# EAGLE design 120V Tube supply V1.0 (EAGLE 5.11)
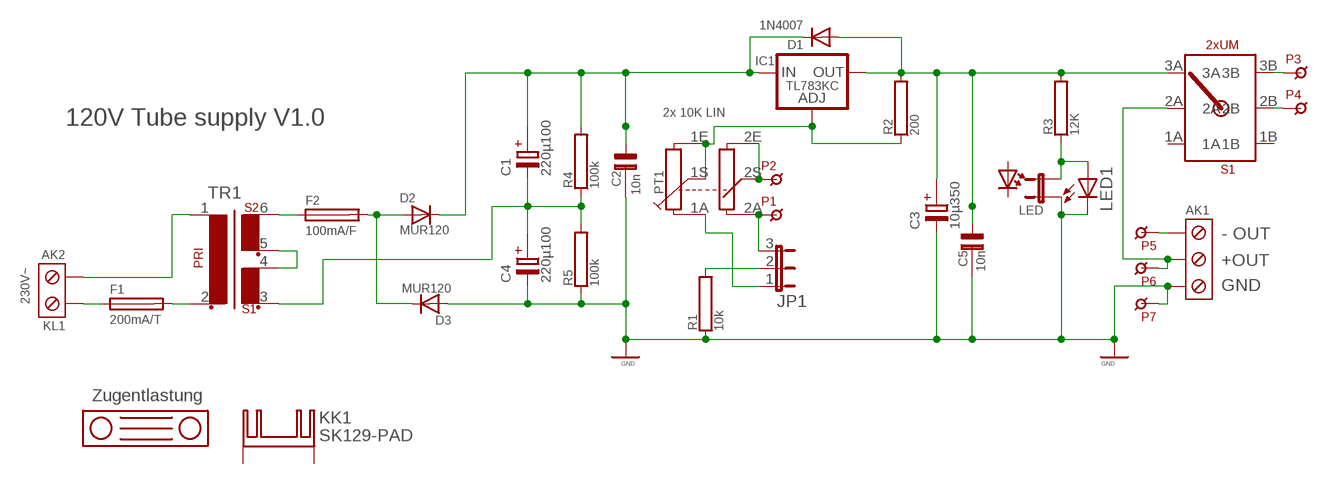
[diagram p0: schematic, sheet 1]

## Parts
AK1  KLEMME3STANDART  [KLEMME3]
AK2  KL1  KLEMME2RM5  [KLEMME2]
C1  220µ100  E7,5-16  [E7,5-16]
C2  10n  C2,5/55/2  [C2,5/5-2]
C3  10µ350  E5-13  [E5-13]
C4  220µ100  E7,5-16  [E7,5-16]
C5  10n  C2,5/55/2  [C2,5/5-2]
D1  1N4007  1N4004  [DO41-10]
D2  MUR120  MUR150RL  [DO41-10]
D3  MUR120  MUR150RL  [DO41-10]
F1  200mA/T  SH22,5A  [SH22,5A]
F2  100mA/F  SH22,5A  [SH22,5A]
IC1  TL783KC  LM317TS  [317TS]
JP1  JP2E  [JP2]
KK1  SK129-PAD  [SK129]
LED  JP1E  [JP1]
LED1  LED3MM  [LED3MM]
P1  AP1_GP13  [PUNKT13]
P2  AP1_GP13  [PUNKT13]
P3  AP1_GP13  [PUNKT13]
P4  AP1_GP13  [PUNKT13]
P5  AP1_GP13  [PUNKT13]
P6  AP1_GP13  [PUNKT13]
P7  AP1_GP13  [PUNKT13]
PT1  2x 10K LIN  BR2G20BU  [BR2G20BU]
R1  10k  0207/10RD  [0207/10]
R2  200  0207/10RD  [0207/10]
R3  12K  0414/15  [0414/15]
R4  100k  0207/10RD  [0207/10]
R5  100k  0207/10RD  [0207/10]
S1  2xUM  S-2PRINT  [S-2PRINT]
TR1  EI48-2  [EI48-2]
U$2  KAZU0442  [KAZU0442]

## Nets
GND: AK1.1 C2.1 C3.- C4.- C5.1 D3.A LED1.K(C) LED.1 P7.1 R1.1 R5.1
N$1: TR1.4 TR1.5
N$2: P3.1 S1.3B
N$3: F2.1 TR1.6
N$4: AK2.1 TR1.1
N$5: F1.2 TR1.2
N$6: AK2.2 F1.1
N$7: C3.+ C5.2 C5.3 D1.A IC1.2(OUT) R2.2 R3.2 S1.3A
N$8: D2.A D3.C F2.2
N$9: JP1.1 PT1.1A
N$10: C1.- C4.+ R4.1 R5.2 TR1.3
N$11: JP1.3 P1.1 PT1.2A
N$12: AK1.2 P6.1 S1.2A
N$13: LED1.A LED.2 R3.1
N$14: JP1.2 R1.2
N$15: IC1.1(ADJ) PT1.1E PT1.1S R2.1
N$16: P4.1 S1.2B
N$17: AK1.3 P5.1
N$19: P2.1 PT1.2E PT1.2S
VCC: C1.+ C2.2 C2.3 D1.C D2.C IC1.3(IN) R4.2
Unconnected: KK1.A2,5(K) KK1.B2,5(K) S1.1A S1.1B

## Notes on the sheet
- 120V Tube supply V1.0
- - OUT
- +OUT
- GND
- 230V~
- Zugentlastung

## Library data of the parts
AK1 = VERBINDE:KLEMME3
AK2 = VERBINDE:KLEMME2
C1 C4 = Elkos:E7,5-16
C2 C5 = CAP-Kondensatoren:C2,5/5
C3 = Elkos:E5-13
D1 = diode:1N4004: DIODE
D2 D3 = diode:MUR150RL: DIODE
F1 F2 = fuse:SH22,5A: FUSE HOLDER; MPN: 0031.7701.11; OC_FARNELL: unknown; OC_NEWARK: 04F1224
IC1 = v-reg:LM317TS: VOLTAGE REGULATOR
JP1 = jumper:JP2E: JUMPER
KK1 = heatsink:SK129-PAD: HEATSINK
LED = jumper:JP1E: JUMPER
LED1 = led:LED: LED
P1-P7 = VERBINDE:AP1_G
PT1 = Potentiometer-piher:BR2G20BU
R1 R2 R4 R5 = R:0207/10
R3 = R:0414/15
S1 = Schalter:S-2PRINT
TR1 = trafo:EI48-2: TRANSFORMER 1 primary winding, 2 secondary windings ERA
U$2 = MB:KAZU0442

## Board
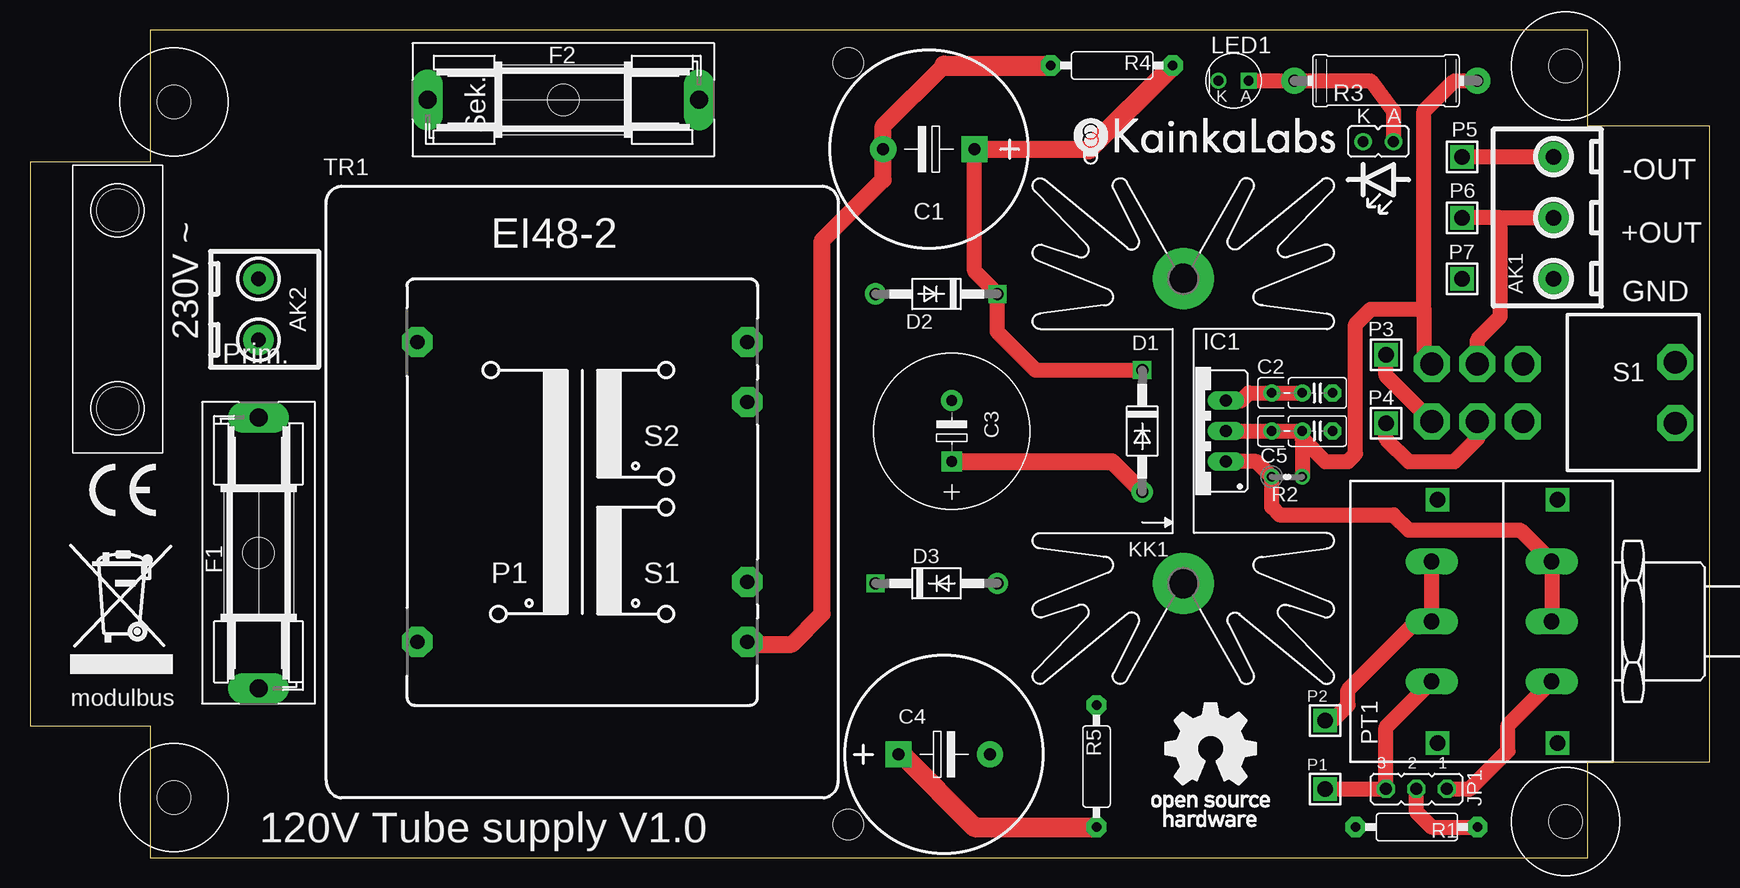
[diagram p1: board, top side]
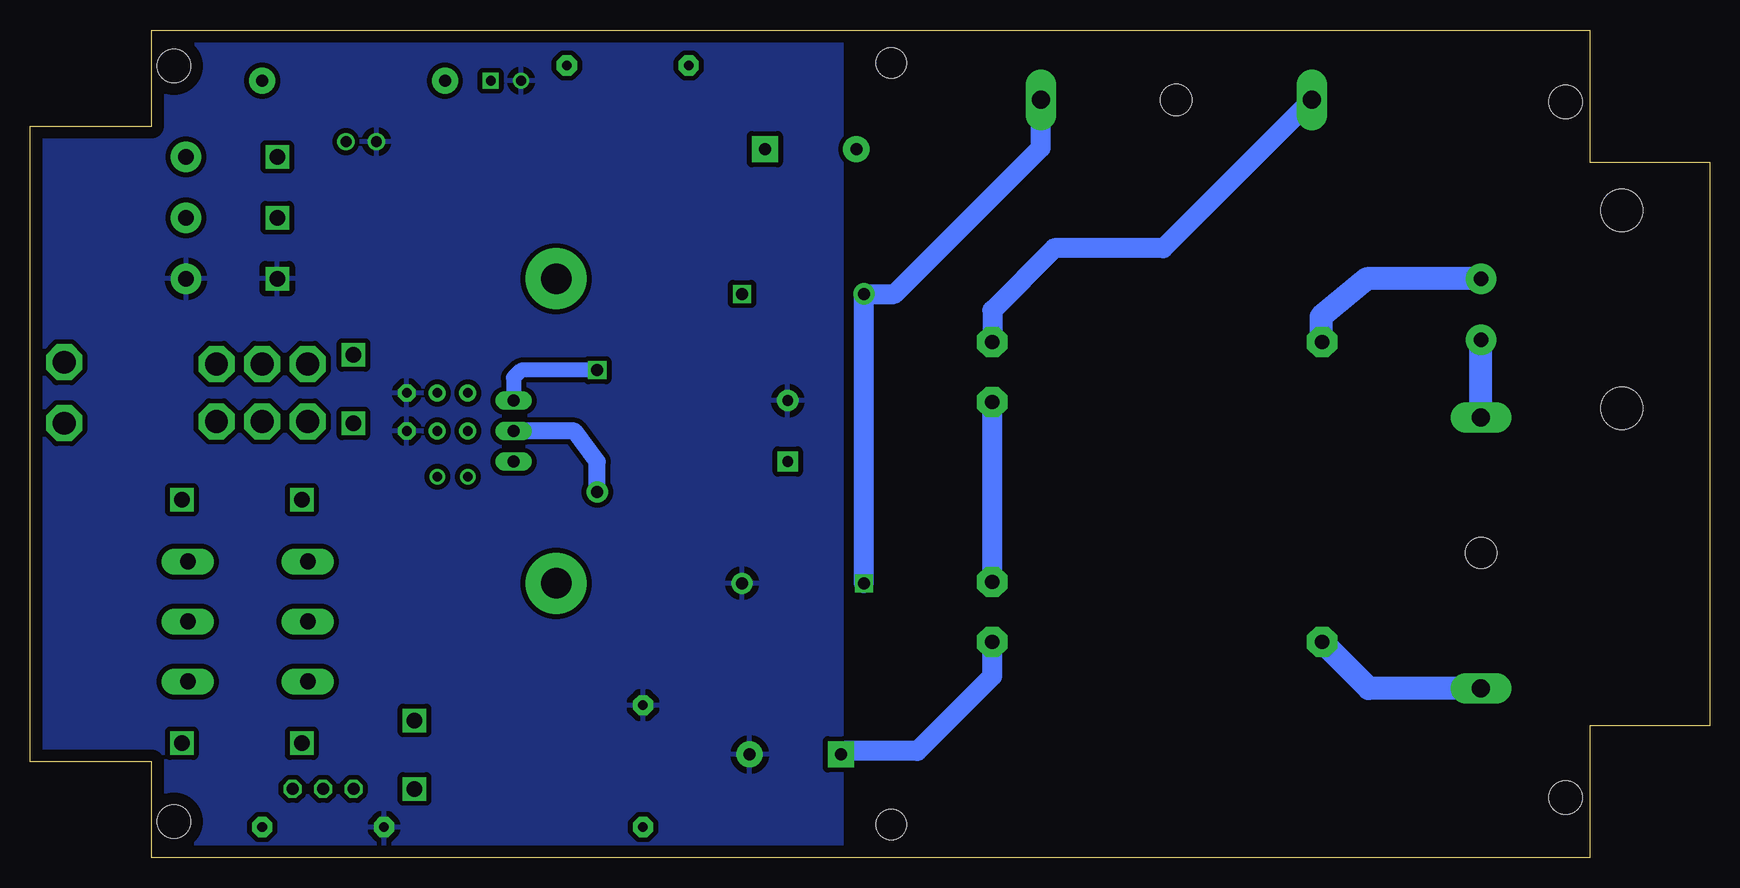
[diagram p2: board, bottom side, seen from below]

Size 140 x 69 mm. Coordinates in mm from the lower left corner, seen from the top.
Copper layers (1*16): Top 0.035mm / dielectric 1.5mm / Bottom 0.035mm
Design rules "default": minimum track width 10mil, minimum drill 23mil, track to track 8mil, track to pad 8mil, pad to pad 8mil, via to via 8mil, smd to smd 8mil, copper to edge 40mil, drill to drill 8mil, minimum pad ring 10mil, minimum via ring 8mil, stop-mask expansion 4mil, vias tented up to drill 0mil, thermal gap 20mil

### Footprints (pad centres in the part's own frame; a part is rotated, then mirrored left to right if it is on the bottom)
KLEMME3 = drill 1.3 pad 2.54 round: 1 0,0; 2 5.08,0; 3 10.16,0
KLEMME2 = drill 1.2 pad 2.54 round: 1 0,0; 2 5.08,0
E7,5-16 = drill 1 pad 2.184 square: + -3.81,0 | drill 1 pad 2.184 round: - 3.81,0
C2,5/5-2 = drill 0.8 pad 1.422 octagon: 1 -2.54,0 | drill 0.8 pad 1.422 round: 2 0,0; 3 2.54,0
E5-13 = drill 0.9 pad 1.676 square: + -2.54,0 | drill 0.9 pad 1.778 round: - 2.54,0
DO41-10 = drill 1 pad 1.778 round: A 5.08,0 | drill 1 square: C -5.08,0
SH22,5A = drill 1.5 pad 2.54 long: 1 -11.3,0; 2 11.3,0 | hole 2.6: 0,0
317TS = drill 1.016 long: 1 -2.54,-2.54; 2 0,-2.54; 3 2.54,-2.54
JP2 = drill 1 octagon: 1 -2.54,0; 2 0,0; 3 2.54,0
SK129 = drill 2.54 pad 5.08 round: A2,5 -12.7,-0.889; B2,5 12.7,-0.889
JP1 = drill 0.914 round: 1 0,-1.27; 2 0,1.27
LED3MM = drill 0.8 square: A -1.27,0 | drill 0.8 round: K 1.27,0
PUNKT13 = drill 1.3 pad 1.778 square: 1 0,0
BR2G20BU = drill 1.3 pad 2.184 long: 1A 10,-5; 1E 10,5; 1S 10,0; 2A 0,-5; 2E 0,5; 2S 0,0 | drill 1.3 square: G1 0.5,10.15; G2 10.5,10.15; G3 0.5,-10.15; G4 10.5,-10.15
0207/10 = drill 0.8 pad 1.676 octagon: 1 -5.08,0; 2 5.08,0
0204V = drill 0.8 round: 1 -1.27,0; 2 1.27,0
0414/15 = drill 1 pad 2.159 round: 1 -7.62,0; 2 7.62,0
S-2PRINT = drill 1.9 pad 3 octagon: 1A 12.7,-2.4; 1B 12.7,2.4; 2A 16.5,-2.4; 2B 16.5,2.4; 3A 20.3,-2.4; 3B 20.3,2.4; P$1 0,2.54; P$2 0,-2.54
EI48-2 = drill 1.2 pad 2.54 octagon: 1 -13.75,12.5; 2 -13.75,-12.5; 3 13.75,-12.5; 4 13.75,-7.5; 5 13.75,7.5; 6 13.75,12.5
KAZU0442 = hole 3.5: 0,0; 16.5,0
WALL3-BO440 = hole 2.5: 71.8,2.75; 71.8,66.25 | hole 2.8: 12,66; 12,3; 128,6; 128,64

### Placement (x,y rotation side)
AK1  127,48.26 90 top
AK2  19.05,48.26 270 top
C1  74.93,59.05 180 top
C2  106.05,38.73 180 top
C3  76.83,35.56 90 top
C4  76.2,8.6 0 top
C5  106.05,35.56 180 top
D1  92.71,35.56 270 top
D2  75.56,46.99 180 top
D3  75.56,22.86 0 top
F1  19.05,25.4 270 top
F2  44.45,63.18 0 top
IC1  97.16,35.56 90 top
JP1  115.57,5.71 180 top
KK1  95.25,35.56 90 top
LED  112.39,59.69 270 top
LED1  100.33,64.77 180 top
P1  107.95,5.71 0 top
P2  107.95,11.43 0 top
P3  113.03,41.91 0 top
P4  113.04,36.19 0 top
P5  119.38,58.42 0 top
P6  119.38,53.34 0 top
P7  119.38,48.26 0 top
PT1  116.85,19.69 0 top
R1  115.57,2.54 0 top
R2  200  [0204V]  104.78,31.75 0 top
R3  113.03,64.77 0 top
R4  90.17,66.04 0 top
R5  88.9,7.62 270 top
S1  137.16,38.76 180 top
TR1  46.04,30.48 0 top
U$2  7.3,37.47 90 top
U$3  [WALL3-BO440]  140,69 180 top
U$4  [KAINKALABS22X4]  87,57.78 0 top
U$5  [EAR]  3.38,15.36 0 top
U$6  [OSH1]  93.47,2.54 0 top
U$7  [LED]  114.94,56.52 180 top
U$8  [CE6MM]  4.96,28.5 0 top

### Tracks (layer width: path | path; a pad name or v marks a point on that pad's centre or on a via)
GND
  pour Bottom (isolate 0.406): 72.41,69 72.41,0.38 130,0 130,8.38 139.83,8.38 139.83,60.96 130,60.96 130,69
N$1
  Bottom 1.676: TR1.4 TR1.5
N$2
  Top 1.27: P3.1 113.03,40.18 S1.3B
N$3
  Bottom 1.676: TR1.6 59.79,45.62 54.61,50.8 45.53,50.8 F2.1
N$4
  Bottom 1.93: AK2.1 28.57,48.26 32.38,45.09 32.38,43.08 TR1.1
N$5
  Bottom 1.93: F1.2 28.41,14.1 TR1.2
N$6
  Bottom 1.93: F1.1 AK2.2
N$7
  Top 1.27: IC1.2 C5.3 C5.2 | C5.2 R2.2 | R3.2 118.75,64.77 116.2,62.23 116.2,45.72 | 116.2,45.72 116.2,41.8 S1.3A | C5.2 106.05,34.92 107.95,33.02 109.22,33.02 109.86,33.02 110.49,33.66 110.49,44.45 111.76,45.72 116.2,45.72
  Top 1.422: C3.+ 90.17,33.02 D1.A
  Bottom 1.422: D1.A 92.71,33.02 94.61,35.56 IC1.2
N$8
  Bottom 1.676: F2.2 55.75,59.19 67.94,46.99 D2.A D3.C
N$9
  Top 1.27: JP1.1 120.02,5.71 123.19,8.89 123.19,11.03 PT1.1A
N$10
  Top 1.422: 76.2,66.04 71.12,60.96 C1.- 71.12,56.52 66.04,51.44 66.04,20.32 63.5,17.78 59.99,17.78
  Top 1.676: C4.+ 72.68,8.6 78.74,2.54 R5.2 | 76.2,66.04 R4.1
  Top 1.93: TR1.3 59.99,17.78
  Bottom 1.422: 72.1,8.89 C4.+
  Bottom 1.676: TR1.3 59.79,15.14 66.04,8.89 72.1,8.89
N$11
  Top 1.27: P1.1 JP1.3 113.03,10.87 PT1.2A
N$12
  Top 1.27: 122.56,53.34 P6.1 | 122.56,53.34 AK1.2 | S1.2A 120.66,43.19 122.56,45.09 122.56,53.34
N$13
  Top 1.27: LED1.A R3.1 111.76,64.77 113.67,62.23 LED.2
N$14
  Top 1.27: JP1.2 115.57,3.81 116.84,2.54 R1.2
N$15
  Top 1.27: PT1.1S PT1.1E 124.23,27.3 114.94,27.3 113.67,28.57 104.14,28.57 103.5,29.21 R2.1 102.23,33.02 IC1.1
N$16
  Top 1.27: P4.1 113.04,34.91 114.94,33.02 118.75,33.02 120.65,34.92 S1.2B
N$17
  Top 1.27: P5.1 AK1.3
N$19
  Top 1.27: PT1.2E PT1.2S 115.57,19.69 109.86,13.97 109.86,12.7 108.58,11.43 P2.1
VCC
  Top 1.27: C1.+ 78.74,48.9 D2.C 80.64,43.81 83.82,40.64 D1.C | IC1.3 100.97,38.1 101.6,38.73 C2.3 C2.2
  Top 1.422: C1.+ 88.27,59.05
  Top 1.676: 88.27,59.05 R4.2
  Bottom 1.27: D1.C 99.06,40.64 99.69,40.01 IC1.3

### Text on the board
tPlace: Sek. | K | A | -OUT | +OUT | GND | 230V ~ | Prim. | modulbus | 120V Tube supply V1.0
